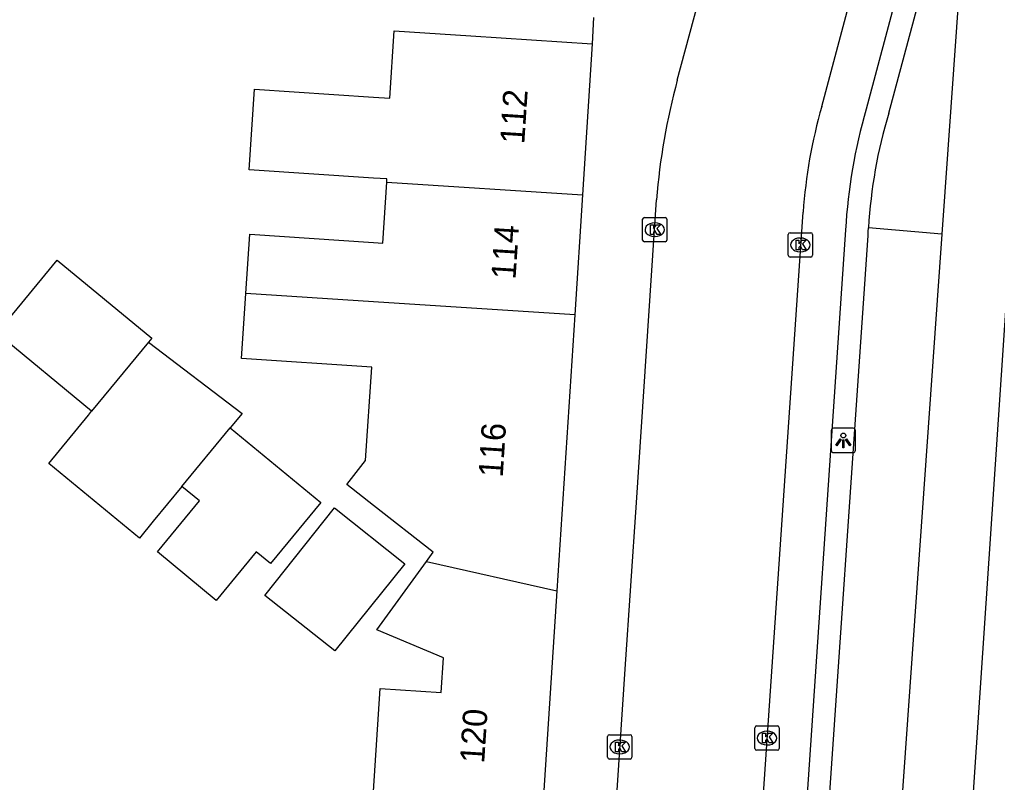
# Model space of a CAD drawing. Extents: x 160158 to 160921, y 381517 to 382041.
# Drawn here: x 160485.46 to 160525.63, y 381852.53 to 381883.87 of the extents above; entities that cross this region are included whole.
import ezdxf

# ---------------------------------------------------------------- set-up
doc = ezdxf.new("R2010")
doc.units = 0
for name, color, linetype in [('IMGEO_Berm_groen', 7, 'Continuous'), ('IMGEO_Berm_open', 7, 'Continuous'), ('IMGEO_Kolk', 7, 'Continuous'), ('IMGEO_Lichtpunt', 7, 'Continuous'), ('IMGEO_Pand', 7, 'Continuous'), ('IMGEO_Pand_nummerreeks', 7, 'Continuous'), ('IMGEO_Parkeervlak_open', 7, 'Continuous'), ('IMGEO_Rijbaan_lokaal_open', 7, 'Continuous'), ('IMGEO_Voetpad_open', 7, 'Continuous')]:
    doc.layers.add(name, color=color, linetype=linetype)

msp = doc.modelspace()

# ---------------------------------------------------------------- linework, layer by layer
at = {"layer": 'IMGEO_Berm_groen'}
for points in [[(160530.336, 381929.12), (160526.984, 381926.458), (160523.346, 381875.055)], [(160532.014, 381924.443), (160531.525, 381926.029), (160530.481, 381926.358), (160529.573, 381925.76), (160523.404, 381833.99)], [(160523.346, 381875.055), (160520.327, 381875.319)], [(160523.346, 381875.055), (160520.714, 381837.873), (160520.28, 381829.952)]]:
    msp.add_lwpolyline(points, dxfattribs=at)
at = {"layer": 'IMGEO_Berm_open'}
for points in [[(160521.159, 381880.018), (160523.89, 381890.182), (160521.239, 381890.925)], [(160517.274, 381830.144), (160518.408, 381847.341), (160520.311, 381874.994), (160520.319, 381875.157), (160520.327, 381875.319)]]:
    msp.add_lwpolyline(points, dxfattribs=at)
msp.add_arc((160540.815, 381874.115), 20.523, 163.283, 176.6357, dxfattribs=at)
at = {"layer": 'IMGEO_Kolk'}
for p, q in [((160511.049, 381874.812), (160511.049, 381875.664)), ((160511.124, 381875.738), (160511.976, 381875.738)), ((160512.05, 381875.664), (160512.05, 381874.812)), ((160511.537, 381875.518), (160511.562, 381875.518)), ((160511.56, 381874.958), (160511.535, 381874.958)), ((160517.03, 381874.187), (160517.03, 381875.039)), ((160517.105, 381875.113), (160517.957, 381875.113)), ((160517.518, 381874.893), (160517.543, 381874.893)), ((160518.031, 381875.039), (160518.031, 381874.187)), ((160511.976, 381874.738), (160511.124, 381874.738)), ((160517.957, 381874.113), (160517.105, 381874.113)), ((160517.541, 381874.333), (160517.516, 381874.333)), ((160515.66, 381853.93), (160515.66, 381854.782)), ((160515.735, 381854.856), (160516.587, 381854.856)), ((160516.661, 381854.782), (160516.661, 381853.93)), ((160509.609, 381853.568), (160509.609, 381854.42)), ((160509.684, 381854.494), (160510.536, 381854.494)), ((160510.61, 381854.42), (160510.61, 381853.568)), ((160516.148, 381854.636), (160516.173, 381854.636)), ((160510.097, 381854.274), (160510.122, 381854.274)), ((160516.171, 381854.076), (160516.146, 381854.076)), ((160510.12, 381853.714), (160510.095, 381853.714)), ((160516.587, 381853.856), (160515.735, 381853.856)), ((160510.536, 381853.494), (160509.684, 381853.494))]:
    msp.add_line(p, q, dxfattribs=at)
for points in [[(160511.049, 381874.812), (160511.049, 381875.664)], [(160511.124, 381875.738), (160511.976, 381875.738)], [(160512.05, 381875.664), (160512.05, 381874.812)], [(160511.37, 381875.438), (160511.493, 381875.438), (160511.493, 381875.287), (160511.623, 381875.438), (160511.787, 381875.438), (160511.641, 381875.287), (160511.794, 381875.038), (160511.642, 381875.038), (160511.557, 381875.202), (160511.493, 381875.135), (160511.493, 381875.038), (160511.37, 381875.038), (160511.37, 381875.438)], [(160517.03, 381874.187), (160517.03, 381875.039)], [(160517.105, 381875.113), (160517.957, 381875.113)], [(160518.031, 381875.039), (160518.031, 381874.187)], [(160511.976, 381874.738), (160511.124, 381874.738)], [(160517.351, 381874.813), (160517.474, 381874.813), (160517.474, 381874.662), (160517.604, 381874.813), (160517.768, 381874.813), (160517.622, 381874.662), (160517.775, 381874.413), (160517.623, 381874.413), (160517.538, 381874.577), (160517.474, 381874.51), (160517.474, 381874.413), (160517.351, 381874.413), (160517.351, 381874.813)], [(160517.957, 381874.113), (160517.105, 381874.113)], [(160515.66, 381853.93), (160515.66, 381854.782)], [(160515.735, 381854.856), (160516.587, 381854.856)], [(160516.661, 381854.782), (160516.661, 381853.93)], [(160509.609, 381853.568), (160509.609, 381854.42)], [(160509.684, 381854.494), (160510.536, 381854.494)], [(160510.61, 381854.42), (160510.61, 381853.568)], [(160515.981, 381854.556), (160516.104, 381854.556), (160516.104, 381854.405), (160516.234, 381854.556), (160516.398, 381854.556), (160516.252, 381854.405), (160516.405, 381854.156), (160516.253, 381854.156), (160516.168, 381854.32), (160516.104, 381854.253), (160516.104, 381854.156), (160515.981, 381854.156), (160515.981, 381854.556)], [(160509.93, 381854.194), (160510.053, 381854.194), (160510.053, 381854.043), (160510.183, 381854.194), (160510.347, 381854.194), (160510.201, 381854.043), (160510.354, 381853.794), (160510.202, 381853.794), (160510.117, 381853.958), (160510.053, 381853.891), (160510.053, 381853.794), (160509.93, 381853.794), (160509.93, 381854.194)], [(160516.587, 381853.856), (160515.735, 381853.856)], [(160510.536, 381853.494), (160509.684, 381853.494)]]:
    msp.add_lwpolyline(points, dxfattribs=at)
for centre, start, end in [((160511.126, 381875.662), 91.552, 178.448), ((160511.126, 381875.662), 91.552, 178.448), ((160511.974, 381875.662), 1.552, 88.448), ((160511.974, 381875.662), 1.552, 88.448), ((160517.107, 381875.037), 91.552, 178.448), ((160517.107, 381875.037), 91.552, 178.448), ((160517.955, 381875.037), 1.552, 88.448), ((160517.955, 381875.037), 1.552, 88.448), ((160511.126, 381874.814), 181.552, 268.448), ((160511.126, 381874.814), 181.552, 268.448), ((160511.974, 381874.814), 271.552, 358.448), ((160511.974, 381874.814), 271.552, 358.448), ((160517.107, 381874.189), 181.552, 268.448), ((160517.107, 381874.189), 181.552, 268.448), ((160517.955, 381874.189), 271.552, 358.448), ((160517.955, 381874.189), 271.552, 358.448), ((160515.737, 381854.78), 91.552, 178.448), ((160515.737, 381854.78), 91.552, 178.448), ((160516.585, 381854.78), 1.552, 88.448), ((160516.585, 381854.78), 1.552, 88.448), ((160509.686, 381854.418), 91.552, 178.448), ((160509.686, 381854.418), 91.552, 178.448), ((160510.534, 381854.418), 1.552, 88.448), ((160510.534, 381854.418), 1.552, 88.448), ((160509.686, 381853.57), 181.552, 268.448), ((160509.686, 381853.57), 181.552, 268.448), ((160510.534, 381853.57), 271.552, 358.448), ((160510.534, 381853.57), 271.552, 358.448), ((160515.737, 381853.932), 181.552, 268.448), ((160515.737, 381853.932), 181.552, 268.448), ((160516.585, 381853.932), 271.552, 358.448), ((160516.585, 381853.932), 271.552, 358.448)]:
    msp.add_arc(centre, 0.0765, start, end, dxfattribs=at)
for centre, major_axis, ratio, start_param, end_param in [((160511.536, 381875.238), (-0.387, 0.002), 0.722429, 4.712389, 7.853982), ((160511.561, 381875.238), (-0.39, 0.002), 0.717154, 1.570796, 4.712389), ((160517.517, 381874.613), (-0.387, 0.002), 0.722429, 4.712389, 7.853982), ((160517.542, 381874.613), (-0.39, 0.002), 0.717154, 1.570796, 4.712389), ((160516.147, 381854.356), (-0.387, 0.002), 0.722429, 4.712389, 7.853982), ((160516.172, 381854.356), (-0.39, 0.002), 0.717154, 1.570796, 4.712389), ((160510.096, 381853.994), (-0.387, 0.002), 0.722429, 4.712389, 7.853982), ((160510.121, 381853.994), (-0.39, 0.002), 0.717154, 1.570796, 4.712389)]:
    msp.add_ellipse(centre, major_axis=major_axis, ratio=ratio, start_param=start_param, end_param=end_param, dxfattribs=at)
at = {"layer": 'IMGEO_Lichtpunt'}
for p, q in [((160518.797, 381866.985), (160518.797, 381866.178)), ((160518.797, 381866.985), (160518.797, 381866.178)), ((160519.699, 381867.08), (160518.891, 381867.08)), ((160519.699, 381867.08), (160518.891, 381867.08)), ((160519.793, 381866.178), (160519.793, 381866.985)), ((160519.793, 381866.178), (160519.793, 381866.985)), ((160518.891, 381866.084), (160519.699, 381866.084)), ((160518.891, 381866.084), (160519.699, 381866.084))]:
    msp.add_line(p, q, dxfattribs=at)
for points in [[(160519.171, 381866.649), (160519.21, 381866.621), (160519.022, 381866.359), (160518.984, 381866.386), (160519.171, 381866.649)], [(160519.273, 381866.601), (160519.32, 381866.601), (160519.32, 381866.279), (160519.273, 381866.279), (160519.273, 381866.601)], [(160519.383, 381866.621), (160519.421, 381866.648), (160519.608, 381866.386), (160519.569, 381866.358), (160519.383, 381866.621)]]:
    msp.add_lwpolyline(points, dxfattribs=at)
msp.add_circle((160519.296, 381866.783), 0.0994, dxfattribs=at)
for centre, start, end in [((160518.891, 381866.985), 90, 180), ((160518.891, 381866.985), 90, 180), ((160519.699, 381866.985), 0, 90), ((160519.699, 381866.985), 0, 90), ((160518.891, 381866.178), 180, 270), ((160518.891, 381866.178), 180, 270), ((160519.699, 381866.178), 270, 0), ((160519.699, 381866.178), 270, 360)]:
    msp.add_arc(centre, 0.0946, start, end, dxfattribs=at)
at = {"layer": 'IMGEO_Pand'}
for points in [[(160500.541, 381877.188), (160500.55, 381877.32), (160500, 381877.356), (160494.887, 381877.699), (160495.109, 381881.006), (160500, 381880.677), (160500.666, 381880.634), (160500.846, 381883.403), (160503.993, 381883.199), (160508.982, 381882.876)], [(160508.982, 381882.876), (160508.58, 381876.669)], [(160494.752, 381872.618), (160494.916, 381875.06), (160500, 381874.712), (160500.38, 381874.687), (160500.541, 381877.188)], [(160500.541, 381877.188), (160508.58, 381876.669)], [(160508.58, 381876.669), (160508.261, 381871.744)], [(160488.417, 381867.777), (160484.527, 381870.981), (160487.004, 381873.988), (160490.894, 381870.783), (160490.756, 381870.616)], [(160502.175, 381861.609), (160502.453, 381861.99), (160500, 381863.909), (160498.898, 381864.771), (160499.672, 381865.759), (160499.929, 381869.589), (160494.573, 381869.95), (160494.752, 381872.618)], [(160508.261, 381871.744), (160500, 381872.278), (160494.752, 381872.618)], [(160508.261, 381871.744), (160507.527, 381860.411)], [(160490.756, 381870.616), (160488.417, 381867.777)], [(160490.756, 381870.616), (160494.595, 381867.689), (160494.107, 381867.097)], [(160492.127, 381864.694), (160490.949, 381863.264), (160490.38, 381862.573), (160486.657, 381865.64), (160488.288, 381867.62), (160488.417, 381867.777)], [(160494.107, 381867.097), (160497.833, 381864.026), (160495.771, 381861.523), (160495.179, 381862.012), (160493.531, 381860.012), (160491.117, 381862.002), (160492.847, 381864.101), (160492.127, 381864.694)], [(160492.127, 381864.694), (160494.107, 381867.097)], [(160498.39, 381863.811), (160501.283, 381861.513), (160498.405, 381857.94), (160495.537, 381860.219), (160498.39, 381863.811)], [(160499.779, 381848.873), (160500, 381852.181), (160500.273, 381856.394), (160502.782, 381856.231), (160502.874, 381857.649), (160500.129, 381858.808), (160502.175, 381861.609)], [(160502.175, 381861.609), (160507.527, 381860.411)], [(160507.527, 381860.411), (160506.751, 381848.424)]]:
    msp.add_lwpolyline(points, dxfattribs=at)
at = {"layer": 'IMGEO_Parkeervlak_open'}
for points in [[(160522.041, 381886.959), (160520.235, 381880.184)], [(160519.387, 381875.229), (160517.479, 381847.224), (160515.937, 381823.215)]]:
    msp.add_lwpolyline(points, dxfattribs=at)
msp.add_arc((160541.984, 381873.912), 22.636, 163.9131, 176.6639, dxfattribs=at)
at = {"layer": 'IMGEO_Rijbaan_lokaal_open'}
for points in [[(160518.409, 381880.302), (160521.037, 381890.167)], [(160512.476, 381881.382), (160514.562, 381889.13)], [(160507.968, 381820.837), (160508.946, 381836.272), (160510.338, 381857.185), (160510.794, 381864.027), (160511.622, 381876.467)], [(160513.972, 381820.522), (160515.631, 381846.447), (160517.644, 381875.952)]]:
    msp.add_lwpolyline(points, dxfattribs=at)
for centre, radius, start, end in [((160538.72, 381874.29), 27.186, 164.8787, 175.4074), ((160538.457, 381874.534), 20.861, 163.9491, 176.1025)]:
    msp.add_arc(centre, radius, start, end, dxfattribs=at)
at = {"layer": 'IMGEO_Voetpad_open'}
msp.add_lwpolyline([(160509.028, 381883.948), (160508.982, 381882.876)], dxfattribs=at)

# ---------------------------------------------------------------- texts
at = {"layer": 'IMGEO_Pand_nummerreeks'}
for s, rotation, p in [('112', 86.2944, (160506.188, 381878.738)), ('114', 86.294, (160505.829, 381873.176)), ('116', 86.2943, (160505.302, 381865.047)), ('120', 86.296, (160504.541, 381853.3))]:
    msp.add_text(s, height=1, rotation=rotation, dxfattribs=at).set_placement(p)

doc.saveas('drawing.dxf')
